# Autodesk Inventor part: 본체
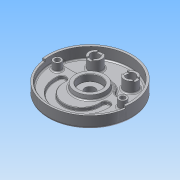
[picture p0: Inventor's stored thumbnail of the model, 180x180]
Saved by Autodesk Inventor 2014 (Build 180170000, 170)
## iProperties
Created: 2015-06
Part Number: 본체
Material: 알루미늄 6061
Document SubType Name: Modeling
Designer: Administrator
Density: 2.71 g/cm^3
Appearance: 알루미늄 - 평지
Mass: 1070.21 g
Surface Area: 1030.16 cm^2
Volume: 394.913 cm^3
Author: Administrator
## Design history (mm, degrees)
sketch "스케치1"
  geometry: C1 r 95 at (0, 0); 1 further point
  constraints: 1 centre point, 1 coincident
  dimensions: "d0" = 190 diameter of C1
extrude "돌출1" new body sketch "스케치1" distance "d1" = 32; taper "d2" = 0 deg
sketch "스케치2"
  geometry: L1 (45.033, 16)-(75.657, 16); L2 (-45.033, 16)-(-75.657, 16); L3 (0, 0)-(-95, 0); L4 (0, 0)-(95, 0); L5 (0, 0)-(-94.075, -13.221); L6 (0, 0)-(94.075, -13.221); C1 r 90 at (0, 0); A1 r 95 centre (0, 0) between (-95, 0) and (95, 0) reference; A2 r 90 centre (0, 0) between (85.114, 29.25) and (-85.114, 29.25); A3 r 42 centre (0, 0) between (36.373, 21) and (-36.373, 21); A4 r 10 centre (-75.657, 26) between (-85.114, 29.25) and (-75.657, 16); A5 r 10 centre (-45.033, 26) between (-45.033, 16) and (-36.373, 21); A6 r 10 centre (45.033, 26) between (36.373, 21) and (45.033, 16); A7 r 10 centre (75.657, 26) between (75.657, 16) and (85.114, 29.25); 4 further points
  constraints: 20 point on circle, 12 end point, 8 tangent, 7 centre point, 4 point on line, 3 coincident, 3 collinear, 2 equal radius, 1 horizontal, 1 parallel
  dimensions: "d3" = 180 diameter of A2; "d4" = 84 diameter of A3; "d5" = 16 distance from line of A1.centre L2; "d6" = 10 radius of A4; "d7" = 10 radius of A5; "d15" = 180 diameter of C1; "d43" = 8 deg angle of L5 L3; "d44" = 8 deg angle of L6 L4
extrude "돌출2" cut sketch "스케치2" distance "d9" = 25; taper "d10" = 0 deg
sketch "스케치3"
  geometry: C1 r 95 at (0, 0) reference; C2 r 26 at (0, 0)
  constraints: 1 centre point, 1 coincident
  dimensions: "d11" = 52 diameter of C2
extrude "돌출3" join sketch "스케치3" distance "d12" = 12; taper "d13" = -15 deg
extrude "돌출4" cut sketch "스케치2" distance "d16" = 18; taper "d17" = 0 deg
sketch "스케치4"
  geometry: C1 r 42 at (0, 0); C2 r 35 at (0, 0); A1 r 42 centre (0, 0) between (36.373, 21) and (-36.373, 21) reference
  constraints: 2 centre point, 2 coincident
  dimensions: "d18" = 84 diameter of C1; "d19" = 70 diameter of C2
extrude "돌출5" join sketch "스케치4" distance "d20" = 10; taper "d21" = -10 deg
sketch "스케치5"
  geometry: C1 r 35 at (0, 0) reference; A1 r 9 centre (49.749, -14) between (58.704, -13.1) and (40.794, -14.9); A2 r 9 centre (-49.749, -14) between (-40.794, -14.9) and (-58.704, -13.1); A3 r 59 centre (0, -19) between (-58.704, -13.1) and (58.704, -13.1); A4 r 41 centre (0, -19) between (-40.794, -14.9) and (40.794, -14.9)
  constraints: 8 point on circle, 4 centre point, 3 tangent, 1 coincident, 1 equal radius, 1 horizontal alignment, 1 vertical alignment
  dimensions: "d22" = 19 distance of A3.centre C1.centre; "d23" = 118 diameter of A3; "d24" = 82 diameter of A4; "d25" = 5 vertical distance of A3.centre A1.centre
extrude "돌출6" cut sketch "스케치5" distance "d26" = 7; taper "d27" = 0 deg
sketch "스케치6"
  geometry: C1 r 15 at (-40, 52); C2 r 15 at (40, 52); A1 r 42 centre (0, 0) between (36.373, 21) and (-36.373, 21) reference
  constraints: 2 centre point, 1 equal radius, 1 horizontal alignment
  dimensions: "d28" = 52 vertical distance of C2.centre A1.centre; "d29" = 30 diameter of C2; "d30" = 80 distance of C2.centre C1.centre; "d31" = 40 horizontal distance of C2.centre A1.centre
extrude "돌출7" join sketch "스케치6" stored distance "d32" = 7; taper "d33" = 0 deg
sketch "스케치7"
  geometry: C1 r 35 at (0, 0) reference; C2 r 9 at (-74, 0); C3 r 9 at (74, 0)
  constraints: 2 centre point, 2 horizontal alignment, 1 equal radius
  dimensions: "d34" = 18 diameter of C2; "d35" = 148 distance of C3.centre C2.centre; "d36" = 74 distance of C2.centre C1.centre
extrude "돌출8" join sketch "스케치7" stored distance "d37" = 7; taper "d38" = 0 deg
sketch "스케치9"
  geometry: L1 (0, 0)-(-95, 0); L2 (0, 0)-(95, 0); L3 (0, 0)-(-94.075, -13.221); L4 (0, 0)-(94.075, -13.221); C1 r 90 at (0, 0) reference; A1 r 95 centre (0, 0) between (-95, 0) and (95, 0) reference
  constraints: 8 end point, 4 point on circle, 1 collinear, 1 horizontal
  dimensions: "d45" = 8 deg angle of L1 L3; "d46" = 8 deg angle of L2 L4
extrude "돌출9" cut sketch "스케치9" distance "d47" = 5; taper "d48" = 0 deg
hole "구멍1" diameter "d51" = 23; stored, may be unused: countersink angle "d55" = 90 deg, drill point angle "d57" = 118 deg; dims "d49" = 10, "d50" = 10, "d52" = 6, "d53" = 50, "d54" = 15, "d56" = 8
hole "구멍2" diameter "d60" = 20; stored, may be unused: countersink angle "d64" = 90 deg, drill point angle "d66" = 118 deg; dims "d58" = 10, "d59" = 10, "d61" = 6, "d62" = 50, "d63" = 15, "d65" = 8
hole "구멍3" diameter "d69" = 20; stored, may be unused: countersink angle "d73" = 90 deg, drill point angle "d75" = 118 deg; dims "d67" = 10, "d68" = 10, "d70" = 6, "d71" = 50, "d72" = 15, "d74" = 8
sketch "스케치10"
  geometry: C1 r 9 at (-74, 0) reference; C2 r 9 at (74, 0) reference; 2 further points
  constraints: 2 coincident
hole "구멍4" sketch "스케치10" at (-74, 0), (74, 0) diameter "d76" = 11; stored, may be unused: countersink angle "d80" = 90 deg, drill point angle "d82" = 118 deg; dims "d77" = 6, "d78" = 18, "d79" = 11, "d81" = 8
sketch "스케치11"
  geometry: L1 (-6, 13.748)-(-6, -13.748); L2 (6, 13.748)-(6, -13.748); L3 (66.252, 6)-(93.748, 6); L4 (93.748, -6)-(66.252, -6); C1 r 10 at (0, 0) reference; C2 r 10 at (80, 0) reference; A1 r 15 centre (0, 0) between (-6, 13.748) and (-6, -13.748) reference; A2 r 15 centre (80, 0) between (66.252, 6) and (93.748, 6) reference; 1 further point
  constraints: 8 end point, 8 point on circle, 2 parallel, 1 perpendicular, 1 vertical
  dimensions: "d83" = 12 distance between parallel lines of L2 L1; "d84" = 6 distance from line of L1 C1.centre; "d85" = 12 distance between parallel lines of L4 L3; "d86" = 6 distance from line of L3 C2.centre
extrude "돌출10" cut sketch "스케치11" distance "d87" = 3; taper "d88" = 0 deg
fillet "모깎기1" dims "d89" = 5
fillet "모깎기2" dims "d90" = 3, "d91" = 1, "d92" = 0.3
chamfer "모따기1" distance "d93" = 1; stored, may be unused: second distance "d94" = 2, angle "d95" = 45 deg
sketch "스케치12"
  geometry: C1 r 28.302 at (0, 0) reference; C2 r 68 at (0, 0)
  constraints: 1 centre point, 1 coincident, 1 other
  dimensions: "d96" = 136 diameter of C2
feature "엠보싱1" sketch "스케치12" dims "d97" = 0.5, "d98" = 0
node "솔리드1"
node "투영된 루프1"
